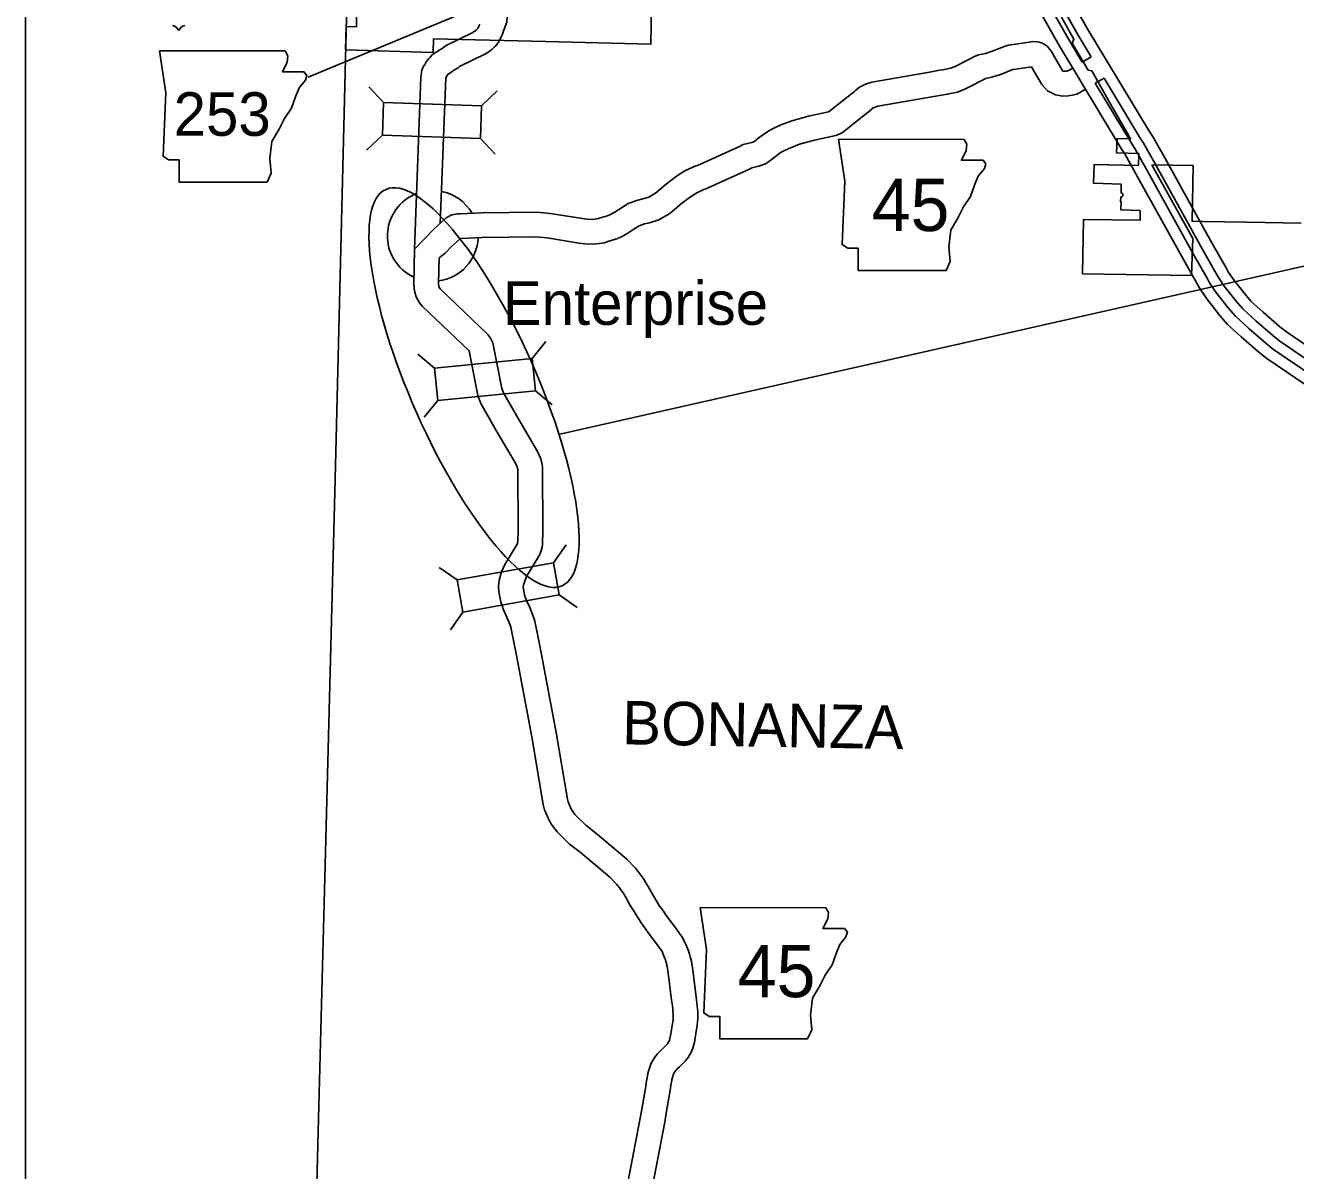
# Model space of a CAD drawing. Extents: x 1370567 to 1373900, y 377514 to 379648.
# Drawn here: x 1370727.3 to 1370881.3, y 379160.9 to 379299.7 of the extents above; entities that cross this region are included whole.
import ezdxf

# ---------------------------------------------------------------- set-up
doc = ezdxf.new("R2010")
doc.units = 0
for name, color, linetype in [('Default', 7, 'Continuous'), ('Survey Names', 7, 'Continuous'), ('Survey Symbols', 7, 'Continuous')]:
    doc.layers.add(name, color=color, linetype=linetype)

msp = doc.modelspace()

# ---------------------------------------------------------------- linework, layer by layer
at = {"layer": 'Default'}
for p, q in [((1370781.87, 379299.11), (1370781.85, 379299.1)), ((1370783.67, 379296.71), (1370783.37, 379296.48)), ((1370770.71, 379290.38), (1370768.91, 379292.31)), ((1370782.59, 379290.01), (1370784.51, 379291.81)), ((1370770.59, 379286.42), (1370768.66, 379284.62)), ((1370782.46, 379286.05), (1370784.27, 379284.12)), ((1370788.74, 379259.38), (1370790.41, 379261.42)), ((1370776.91, 379258.21), (1370774.87, 379259.89)), ((1370789.13, 379255.44), (1370791.17, 379253.76)), ((1370777.3, 379254.27), (1370775.63, 379252.23)), ((1370791.34, 379234.59), (1370792.85, 379236.76)), ((1370779.64, 379232.51), (1370777.47, 379234.02)), ((1370792.03, 379230.69), (1370794.19, 379229.18)), ((1370780.33, 379228.61), (1370778.82, 379226.45))]:
    msp.add_line(p, q, dxfattribs=at)
for points in [[(1370823.09, 379357.67), (1370856.14, 379299.26)], [(1370820.6, 379353.95), (1370852.66, 379297.29)], [(1370764.84, 379244.73), (1370766.68, 379318.76)], [(1370783.48, 379307.7), (1370783.95, 379306.48), (1370784.35, 379305.49), (1370784.83, 379304.17), (1370785.03, 379303.59), (1370785.23, 379303.14), (1370785.54, 379302.29), (1370785.66, 379301.75), (1370785.7, 379301.32), (1370785.72, 379300.74), (1370785.67, 379300.14), (1370785.21, 379298.97)], [(1370848.48, 379307.47), (1370853.86, 379297.96)], [(1370849.62, 379307.98), (1370854.95, 379298.58)], [(1370767.45, 379300.81), (1370767.42, 379299.56), (1370766.17, 379299.6), (1370766.11, 379296.8), (1370776.72, 379296.46), (1370776.77, 379298.11), (1370790.38, 379297.78), (1370803.15, 379297.46), (1370803.24, 379304.11)], [(1370761.55, 379293.48), (1370782.65, 379302.2)], [(1370782.35, 379299.88), (1370782.3, 379299.71), (1370782.3, 379299.7), (1370782.2, 379299.5), (1370782.16, 379299.41), (1370782.15, 379299.39), (1370782.11, 379299.33), (1370781.97, 379299.19), (1370781.96, 379299.18), (1370781.87, 379299.11)], [(1370852.93, 379300.74), (1370854.44, 379298.07), (1370854.25, 379297.61), (1370856.16, 379294.32), (1370856.62, 379294.23), (1370858.98, 379290.09), (1370860.89, 379286.73), (1370861.31, 379285.99), (1370859.67, 379286.03), (1370859.62, 379284.28), (1370862.31, 379284.2), (1370862.31, 379284.2), (1370862.27, 379282.76), (1370856.9, 379282.89), (1370856.8, 379280.61), (1370860.17, 379280.51), (1370860.16, 379279.44), (1370860.18, 379279.44), (1370860.19, 379279.44), (1370860.21, 379279.44), (1370860.22, 379279.43), (1370860.24, 379279.42), (1370860.25, 379279.42), (1370860.27, 379279.41), (1370860.28, 379279.4), (1370860.29, 379279.39), (1370860.31, 379279.38), (1370860.32, 379279.37), (1370860.33, 379279.36), (1370860.34, 379279.35), (1370860.35, 379279.34), (1370860.36, 379279.32), (1370860.36, 379279.31), (1370860.37, 379279.3), (1370860.38, 379279.28), (1370860.38, 379279.27), (1370860.38, 379279.25), (1370860.39, 379279.24), (1370860.39, 379279.22), (1370860.39, 379279.2), (1370860.39, 379279.19), (1370860.39, 379279.17), (1370860.39, 379279.16), (1370860.38, 379279.14), (1370860.38, 379279.13), (1370860.38, 379279.11), (1370860.37, 379279.1), (1370860.36, 379279.08), (1370860.36, 379279.07), (1370860.35, 379279.06), (1370860.34, 379279.04), (1370860.33, 379279.03), (1370860.32, 379279.02), (1370860.31, 379279.01), (1370860.3, 379279), (1370860.28, 379278.99), (1370860.27, 379278.98), (1370860.26, 379278.97), (1370860.24, 379278.97), (1370860.23, 379278.96), (1370860.21, 379278.95), (1370860.2, 379278.95), (1370860.18, 379278.95), (1370860.17, 379278.95), (1370860.15, 379278.94), (1370860.13, 379278.94), (1370860.12, 379278.94), (1370860.08, 379278.39), (1370860.19, 379278.38), (1370860.14, 379277.39), (1370862.46, 379277.3), (1370862.48, 379276.13), (1370855.61, 379276.23), (1370855.48, 379269.63), (1370868.69, 379269.44), (1370868.88, 379273.91), (1370863.91, 379282.83), (1370863.91, 379282.85), (1370868.91, 379282.76), (1370868.78, 379276.01), (1370870.06, 379275.99), (1370875.4, 379275.9), (1370882.01, 379275.77)], [(1370781.85, 379299.1), (1370781.72, 379299), (1370781.57, 379298.91), (1370781.55, 379298.9), (1370778.29, 379297.31), (1370778.03, 379297.09), (1370777.98, 379297.06), (1370777.82, 379296.96), (1370777.72, 379296.88), (1370777.58, 379296.82), (1370777.27, 379296.6), (1370777.24, 379296.57), (1370777, 379296.47), (1370776.81, 379296.29), (1370776.66, 379296.2), (1370776.36, 379295.91), (1370776.17, 379295.69), (1370776.08, 379295.57), (1370775.89, 379295.33), (1370775.76, 379295.09), (1370775.74, 379295.05), (1370775.54, 379294.79), (1370775.35, 379294.3), (1370775.32, 379294.08), (1370775.26, 379293.73), (1370775.25, 379293.47), (1370774.46, 379272.61)], [(1370785.21, 379298.97), (1370785.14, 379298.68), (1370784.99, 379298.36), (1370784.94, 379298.27), (1370784.86, 379298.06), (1370784.65, 379297.72), (1370784.52, 379297.54), (1370784.33, 379297.27), (1370784.13, 379297.1), (1370784.06, 379297.04), (1370783.88, 379296.87), (1370783.67, 379296.71)], [(1370854.95, 379298.58), (1370856.55, 379295.92)], [(1370856.14, 379299.26), (1370863.52, 379287.01), (1370864.07, 379286.19), (1370865.46, 379283.7), (1370871.21, 379273.32), (1370872.91, 379270.34), (1370873.14, 379269.88), (1370873.78, 379268.95), (1370875.17, 379267.19), (1370875.91, 379266.33), (1370877.4, 379264.96), (1370879.42, 379263.21), (1370880.22, 379262.59), (1370887.22, 379257.82), (1370896.57, 379250.49)], [(1370783.37, 379296.48), (1370783.25, 379296.41), (1370783.17, 379296.37), (1370783.16, 379296.36), (1370783.06, 379296.3), (1370779.94, 379294.77), (1370779.76, 379294.62), (1370779.52, 379294.48), (1370779.46, 379294.44), (1370779.21, 379294.27), (1370779.1, 379294.22), (1370779.04, 379294.17), (1370778.77, 379293.97), (1370778.52, 379293.82), (1370778.5, 379293.79), (1370778.42, 379293.69), (1370778.41, 379293.68), (1370778.26, 379293.41), (1370778.25, 379293.4), (1370778.25, 379293.37), (1370777.58, 379275.74)], [(1370849.54, 379297.8), (1370847.94, 379297.57), (1370846.51, 379297.35), (1370846.09, 379297.24), (1370844.65, 379296.65), (1370843.71, 379296.36), (1370842.88, 379296.18), (1370842.38, 379295.98), (1370840.05, 379294.78), (1370839.46, 379294.55), (1370838.56, 379294.35), (1370838.16, 379294.3), (1370836.92, 379294.07)], [(1370854.3, 379294.57), (1370853.86, 379294.31), (1370853.72, 379294.24), (1370853.6, 379294.21), (1370853.44, 379294.19), (1370853.29, 379294.18), (1370853.16, 379294.21), (1370853.06, 379294.25), (1370853, 379294.33), (1370852.24, 379295.65), (1370851.71, 379296.59), (1370851.26, 379297.19), (1370850.65, 379297.58), (1370850.05, 379297.75), (1370849.54, 379297.8)], [(1370852.66, 379297.29), (1370860.18, 379284.82), (1370860.65, 379284.11), (1370861.97, 379281.75), (1370867.72, 379271.37), (1370869.39, 379268.43), (1370869.7, 379267.83), (1370870.56, 379266.58), (1370872.09, 379264.63), (1370873.04, 379263.54), (1370874.74, 379261.98), (1370876.88, 379260.12), (1370877.86, 379259.36), (1370884.86, 379254.59), (1370894.19, 379247.28)], [(1370853.86, 379297.96), (1370855.46, 379295.3)], [(1370855.46, 379295.3), (1370856.55, 379295.92)], [(1370836.94, 379294.08), (1370829.94, 379292.87), (1370829.15, 379292.61), (1370828.43, 379292.24), (1370828, 379291.91), (1370827.84, 379291.75), (1370826.54, 379290.71)], [(1370849.31, 379294.74), (1370847.12, 379294.41), (1370847.05, 379294.39), (1370845.66, 379293.83), (1370844.49, 379293.46), (1370843.74, 379293.29), (1370843.6, 379293.24), (1370841.29, 379292.04), (1370840.33, 379291.67), (1370839.08, 379291.4), (1370838.63, 379291.34), (1370837.47, 379291.12)], [(1370855.85, 379292), (1370855.25, 379291.66), (1370854.78, 379291.42), (1370854.23, 379291.27), (1370853.73, 379291.2), (1370853.05, 379291.17), (1370852.21, 379291.34), (1370851.22, 379291.8), (1370850.54, 379292.58), (1370849.63, 379294.17), (1370849.31, 379294.74)], [(1370857.01, 379292.73), (1370858.1, 379293.35)], [(1370857.01, 379292.73), (1370861.33, 379285.58), (1370861.82, 379284.82), (1370863.17, 379282.42), (1370868.92, 379272.04), (1370870.6, 379269.09), (1370870.88, 379268.53), (1370871.67, 379267.4), (1370873.15, 379265.51), (1370874.03, 379264.5), (1370875.65, 379263), (1370877.75, 379261.18), (1370878.67, 379260.47), (1370885.67, 379255.7), (1370895.01, 379248.38)], [(1370858.1, 379293.35), (1370862.37, 379286.26), (1370862.89, 379285.47), (1370864.26, 379283.03), (1370870.01, 379272.65), (1370871.7, 379269.68), (1370871.96, 379269.18), (1370872.67, 379268.14), (1370874.11, 379266.31), (1370874.93, 379265.37), (1370876.49, 379263.94), (1370878.55, 379262.15), (1370879.41, 379261.48), (1370886.41, 379256.71), (1370895.76, 379249.39)], [(1370826.54, 379290.71), (1370824.81, 379289.33), (1370824.68, 379289.27), (1370822.27, 379288.76), (1370820.23, 379288.18), (1370818.83, 379287.64), (1370817.89, 379287.22), (1370817.32, 379286.88), (1370816.28, 379286.14), (1370815.7, 379285.67), (1370815.36, 379285.55), (1370814.34, 379285.3), (1370813.89, 379285.07), (1370808.78, 379282.76), (1370808.59, 379282.71), (1370807.26, 379282.1), (1370806.23, 379281.46), (1370804.98, 379280.51), (1370803.68, 379279.4), (1370802.89, 379278.94), (1370802.16, 379278.71), (1370801.54, 379278.57), (1370800.4, 379278.17), (1370799.56, 379277.63), (1370798.69, 379277.07), (1370798.17, 379276.79), (1370797.95, 379276.7)], [(1370837.45, 379291.12), (1370830.67, 379289.95), (1370830.32, 379289.84), (1370830.04, 379289.7), (1370829.99, 379289.66), (1370829.85, 379289.51), (1370828.41, 379288.37)], [(1370828.41, 379288.37), (1370826.33, 379286.71), (1370825.55, 379286.39), (1370823, 379285.85), (1370821.18, 379285.33), (1370819.99, 379284.87), (1370819.28, 379284.55), (1370818.95, 379284.36), (1370818.09, 379283.75), (1370817.41, 379283.19), (1370817.04, 379282.96), (1370816.22, 379282.67), (1370815.39, 379282.47), (1370815.19, 379282.37), (1370809.74, 379279.9), (1370809.56, 379279.86), (1370808.69, 379279.46), (1370807.93, 379278.98), (1370806.86, 379278.17), (1370805.43, 379276.94), (1370804.1, 379276.18), (1370802.95, 379275.82), (1370802.38, 379275.68), (1370801.73, 379275.46), (1370801.19, 379275.11), (1370800.23, 379274.49), (1370799.49, 379274.09), (1370799.15, 379273.94)], [(1370797.97, 379276.7), (1370797.75, 379276.61), (1370797, 379276.41), (1370796.78, 379276.33), (1370796.08, 379276.23), (1370795.42, 379276.25), (1370794.84, 379276.33), (1370790.92, 379276.96), (1370789.29, 379277.1), (1370782.59, 379277.03), (1370779.99, 379276.91), (1370779.72, 379276.92), (1370779, 379276.8), (1370778.32, 379276.41), (1370776.86, 379275.09), (1370774.46, 379272.61)], [(1370799.13, 379273.93), (1370798.72, 379273.77), (1370797.9, 379273.54), (1370797.5, 379273.4), (1370796.23, 379273.22), (1370795.17, 379273.26), (1370794.41, 379273.36), (1370790.55, 379273.98), (1370789.18, 379274.1), (1370782.68, 379274.03), (1370780.03, 379273.91), (1370778.95, 379272.93), (1370778.19, 379272.15), (1370777.44, 379271.56)], [(1370774.46, 379272.61), (1370774.37, 379268.32), (1370774.45, 379267.57), (1370774.65, 379266.84), (1370775.09, 379266.13), (1370775.4, 379265.71), (1370781.07, 379260.32), (1370781.09, 379260.28), (1370782.15, 379254.88), (1370782.53, 379253.9), (1370784.38, 379250.65), (1370786.73, 379246.67), (1370786.93, 379246.24), (1370786.97, 379246.05), (1370786.98, 379245.95), (1370787.04, 379238.5)], [(1370777.44, 379271.56), (1370777.37, 379268.46), (1370777.41, 379268.14), (1370777.43, 379268.05), (1370777.58, 379267.81), (1370777.66, 379267.71), (1370783.33, 379262.31), (1370783.69, 379261.81), (1370783.96, 379261.25), (1370785.05, 379255.71), (1370785.25, 379255.19), (1370786.98, 379252.15), (1370789.38, 379248.08), (1370789.79, 379247.2), (1370789.94, 379246.51), (1370789.98, 379246.12), (1370790.04, 379238.48)], [(1370761.86, 379128.63), (1370761.98, 379133.85), (1370762.81, 379167.24), (1370763.57, 379194.87), (1370764.84, 379244.73)], [(1370787.04, 379238.5), (1370787, 379237.13), (1370786.91, 379236.84), (1370785.43, 379234.37), (1370785.21, 379233.94), (1370785.03, 379233.48), (1370784.72, 379232.49), (1370784.66, 379231.77), (1370784.69, 379231.06), (1370784.92, 379229.87), (1370785.28, 379228.88), (1370785.68, 379228), (1370786.15, 379226.83), (1370786.16, 379226.79), (1370786.61, 379224.57), (1370786.87, 379223.15), (1370788.7, 379213.49), (1370790.09, 379205.29), (1370790.25, 379204.66), (1370790.83, 379203.26), (1370791.22, 379202.72), (1370791.47, 379202.33), (1370791.77, 379201.96), (1370793.26, 379200.49), (1370794.55, 379199.52), (1370798.14, 379196.46)], [(1370790.04, 379238.48), (1370790, 379236.83), (1370789.94, 379236.46), (1370789.65, 379235.58), (1370788.06, 379232.93), (1370787.96, 379232.73), (1370787.87, 379232.49), (1370787.68, 379231.9), (1370787.66, 379231.71), (1370787.68, 379231.42), (1370787.82, 379230.67), (1370788.06, 379230.02), (1370788.44, 379229.19), (1370788.99, 379227.8), (1370789.08, 379227.5), (1370789.56, 379225.13), (1370789.82, 379223.69), (1370791.65, 379214.02), (1370793.03, 379205.92), (1370793.11, 379205.61), (1370793.46, 379204.74), (1370793.71, 379204.4), (1370793.91, 379204.08), (1370793.98, 379204), (1370795.23, 379202.77), (1370796.43, 379201.87), (1370800.2, 379198.66)], [(1370800.2, 379198.66), (1370801.21, 379197.62), (1370801.42, 379197.37), (1370801.56, 379197.21), (1370801.81, 379196.89), (1370802.05, 379196.57), (1370802.34, 379196.14), (1370802.54, 379195.81), (1370802.79, 379195.36), (1370803.5, 379194.12)], [(1370798.14, 379196.46), (1370799, 379195.58), (1370799.14, 379195.42), (1370799.23, 379195.31), (1370799.43, 379195.06), (1370799.59, 379194.84), (1370799.81, 379194.52), (1370799.95, 379194.29), (1370800.18, 379193.88), (1370800.4, 379193.5)], [(1370800.4, 379193.5), (1370800.64, 379193.05), (1370801.01, 379192.45), (1370801.21, 379192.11), (1370801.46, 379191.72), (1370801.7, 379191.33), (1370801.95, 379190.96), (1370802.2, 379190.6), (1370802.48, 379190.22), (1370802.76, 379189.82), (1370803.33, 379189.06), (1370803.84, 379188.37), (1370804.5, 379187.45)], [(1370803.5, 379194.12), (1370803.58, 379194), (1370803.77, 379193.67), (1370803.99, 379193.32), (1370804.2, 379192.98), (1370804.42, 379192.67), (1370804.65, 379192.34), (1370804.92, 379191.97), (1370805.19, 379191.59), (1370805.75, 379190.84), (1370806.27, 379190.13), (1370806.7, 379189.53), (1370806.96, 379189.15)], [(1370806.96, 379189.15), (1370807.41, 379188.22), (1370807.5, 379188.03), (1370807.6, 379187.77), (1370807.72, 379187.44), (1370807.82, 379187.16), (1370807.91, 379186.83), (1370807.99, 379186.57), (1370808.05, 379186.29), (1370808.12, 379185.93), (1370808.18, 379185.51), (1370808.23, 379185.2), (1370808.3, 379184.61), (1370808.38, 379183.92), (1370808.47, 379183.24), (1370808.62, 379181.99), (1370808.72, 379181.23), (1370808.76, 379180.82), (1370808.8, 379180.51), (1370808.82, 379180.21), (1370808.85, 379179.79), (1370808.84, 379179.34), (1370808.8, 379178.95), (1370808.75, 379178.52), (1370808.7, 379178.22), (1370808.64, 379177.8), (1370808.59, 379177.5), (1370808.52, 379177.01), (1370808.41, 379176.42), (1370808.23, 379175.73), (1370807.99, 379175.19), (1370807.83, 379174.91), (1370807.66, 379174.62)], [(1370804.5, 379187.45), (1370804.8, 379186.7), (1370804.89, 379186.44), (1370804.95, 379186.27), (1370805.02, 379186.02), (1370805.08, 379185.83), (1370805.11, 379185.68), (1370805.16, 379185.41), (1370805.21, 379185.08), (1370805.25, 379184.82), (1370805.32, 379184.25), (1370805.4, 379183.54), (1370805.49, 379182.87), (1370805.64, 379181.61), (1370805.74, 379180.88), (1370805.78, 379180.5), (1370805.81, 379180.21), (1370805.83, 379179.99), (1370805.85, 379179.72), (1370805.84, 379179.5), (1370805.82, 379179.28), (1370805.78, 379178.95), (1370805.74, 379178.68), (1370805.68, 379178.27), (1370805.63, 379177.97), (1370805.56, 379177.48), (1370805.48, 379177.07), (1370805.39, 379176.73), (1370805.32, 379176.56), (1370805.16, 379176.28)], [(1370805.16, 379176.28), (1370804.86, 379175.97), (1370804.52, 379175.64), (1370804.18, 379175.32), (1370803.94, 379175.07), (1370803.72, 379174.8), (1370803.56, 379174.57), (1370803.37, 379174.27), (1370803.18, 379173.91), (1370803.03, 379173.58), (1370802.91, 379173.2), (1370802.83, 379172.95), (1370802.74, 379172.53), (1370802.71, 379172.36), (1370802.56, 379171.53)], [(1370807.66, 379174.62), (1370807.29, 379174.17), (1370806.99, 379173.85), (1370806.59, 379173.47), (1370806.3, 379173.19), (1370806.2, 379173.09), (1370806.12, 379172.99), (1370806.04, 379172.88), (1370805.96, 379172.76), (1370805.88, 379172.6), (1370805.83, 379172.5), (1370805.78, 379172.32), (1370805.74, 379172.2), (1370805.68, 379171.94), (1370805.66, 379171.83), (1370805.52, 379171.08)], [(1370802.56, 379171.53), (1370802.51, 379171.1), (1370802.02, 379168.37), (1370801.85, 379167.28), (1370798.42, 379149.33), (1370797.12, 379143.03), (1370797.05, 379142.1), (1370797.13, 379141), (1370798.16, 379136.33)], [(1370805.54, 379171.16), (1370805.47, 379170.65), (1370804.98, 379167.88), (1370804.81, 379166.77), (1370801.36, 379148.75), (1370800.1, 379142.6), (1370800.06, 379142.09), (1370800.09, 379141.73)]]:
    msp.add_lwpolyline(points, dxfattribs=at)
for points in [[(1370743.55, 379296.65), (1370744.31, 379291.58), (1370743.97, 379283.88), (1370744.65, 379283.46), (1370745.92, 379283.46), (1370745.92, 379280.75), (1370756.58, 379280.75), (1370757.09, 379281.85), (1370756.92, 379283.63), (1370757.17, 379285.66), (1370758.1, 379287.26), (1370758.69, 379288.45), (1370759.54, 379289.72), (1370760.05, 379291.07), (1370760.47, 379292.17), (1370761.23, 379293.1), (1370761.4, 379293.69), (1370761.06, 379294.12), (1370758.44, 379294.12), (1370759.03, 379295.3), (1370759.12, 379296.06), (1370758.76, 379296.65)], [(1370770.59, 379286.42), (1370782.46, 379286.05), (1370782.59, 379290.01), (1370770.71, 379290.38)], [(1370825.91, 379285.94), (1370826.67, 379280.86), (1370826.33, 379273.17), (1370827.01, 379272.74), (1370828.27, 379272.74), (1370828.27, 379270.04), (1370838.93, 379270.04), (1370839.44, 379271.14), (1370839.27, 379272.91), (1370839.52, 379274.94), (1370840.46, 379276.55), (1370841.05, 379277.73), (1370841.89, 379279), (1370842.4, 379280.36), (1370842.82, 379281.46), (1370843.59, 379282.39), (1370843.75, 379282.98), (1370843.42, 379283.4), (1370840.79, 379283.4), (1370841.39, 379284.59), (1370841.47, 379285.35), (1370841.12, 379285.93)], [(1370777.3, 379254.27), (1370789.13, 379255.44), (1370788.74, 379259.38), (1370776.91, 379258.21)], [(1370780.33, 379228.61), (1370792.03, 379230.69), (1370791.34, 379234.59), (1370779.64, 379232.51)], [(1370809.12, 379192.79), (1370809.88, 379187.72), (1370809.54, 379180.02), (1370810.22, 379179.59), (1370811.49, 379179.59), (1370811.49, 379176.89), (1370822.15, 379176.89), (1370822.66, 379177.99), (1370822.49, 379179.76), (1370822.74, 379181.79), (1370823.67, 379183.4), (1370824.26, 379184.59), (1370825.11, 379185.85), (1370825.62, 379187.21), (1370826.04, 379188.31), (1370826.8, 379189.24), (1370826.97, 379189.83), (1370826.63, 379190.25), (1370824.01, 379190.25), (1370824.6, 379191.44), (1370824.69, 379192.2), (1370824.34, 379192.78)]]:
    msp.add_lwpolyline(points, close=True, dxfattribs=at)
for centre, radius, start, end in [((1370744.77, 379298.56), 1.24, 28.0342, 72.9864), ((1370746.96, 379298.56), 1.24, 107.0136, 151.9658), ((1370776.68, 379274.22), 5.5, 30.0451, 79.031), ((1370776.68, 379274.22), 5.5, 110.9363, 245.3145), ((1370776.68, 379274.22), 5.5, 277.2419, 357.759)]:
    msp.add_arc(centre, radius, start, end, dxfattribs=at)
at = {"layer": 'Survey Names'}
msp.add_line((1371498.51, 379409.91), (1370792.1, 379250.17), dxfattribs=at)
msp.add_ellipse((1370781.69, 379255.84), major_axis=(10.68, -24.03), ratio=0.289472, dxfattribs=at)
at = {"layer": 'Survey Symbols'}
msp.add_lwpolyline([(1370727.27, 379552.54), (1371456.67, 379552.54), (1371456.67, 378768.06), (1370727.27, 378768.06)], close=True, dxfattribs=at)
msp.add_lwpolyline([(1370727.27, 379552.54), (1371456.67, 379552.54), (1371456.67, 378768.06), (1370727.27, 378768.06)], close=True, dxfattribs=at)
msp.add_lwpolyline([(1370727.27, 379552.54), (1371456.67, 379552.54), (1371456.67, 378768.06), (1370727.27, 378768.06)], close=True, dxfattribs=at)
msp.add_lwpolyline([(1370727.27, 379552.54), (1371456.67, 379552.54), (1371456.67, 378768.06), (1370727.27, 378768.06)], close=True, dxfattribs=at)
msp.add_lwpolyline([(1370727.27, 379552.54), (1371456.67, 379552.54), (1371456.67, 378768.06), (1370727.27, 378768.06)], close=True, dxfattribs=at)
msp.add_lwpolyline([(1370727.27, 379552.54), (1371456.67, 379552.54), (1371456.67, 378768.06), (1370727.27, 378768.06)], close=True, dxfattribs=at)

# ---------------------------------------------------------------- texts
at = {"layer": 'Default'}
for s, height, p in [('253', 5.28, (1370745.25, 379286.36)), ('45', 6.336, (1370829.92, 379274.81)), ('Enterprise', 5.28, (1370785.17, 379263.44)), ('45', 6.336, (1370813.67, 379181.93))]:
    msp.add_text(s, height=height, dxfattribs=at).set_placement(p)
msp.add_text('BONANZA', height=5.28, rotation=359, dxfattribs=at).set_placement((1370799.62, 379212.59))

doc.saveas('drawing.dxf')
